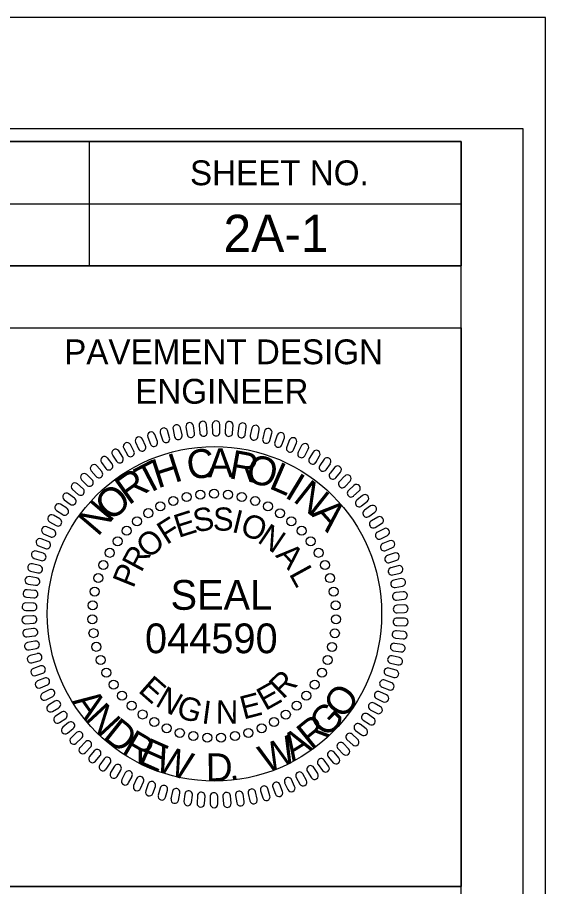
# Model space of a CAD drawing. Extents: x 1901670 to 1902225, y 193498 to 194278.
# Drawn here: x 1902123.59 to 1902134.24, y 194250.51 to 194268.01 of the extents above; entities that cross this region are included whole.
import ezdxf

# ---------------------------------------------------------------- set-up
doc = ezdxf.new("R2010")
doc.units = 0
for name, color, linetype in [('ENG SEALS CELL', 7, 'Continuous'), ('Scratch_Level_3', 7, 'Continuous'), ('Sheet Border Standard 30in CELL', 7, 'Continuous'), ('Sheet Cutting Line CELL', 7, 'Continuous'), ('Sheet Data Field CELL', 7, 'Continuous'), ('Sheet Plot Border Inside CELL', 7, 'Continuous'), ('Sheet Plot Border Outside CELL', 7, 'Continuous'), ('Sheet Sticker Exception Certification CELL', 7, 'Continuous')]:
    doc.layers.add(name, color=color, linetype=linetype)

msp = doc.modelspace()

# ---------------------------------------------------------------- linework, layer by layer
at = {"layer": 'ENG SEALS CELL'}
for p, q in [((1902126.913, 194259.604), (1902126.88, 194259.75)), ((1902126.993, 194259.766), (1902127.017, 194259.618)), ((1902127.166, 194259.642), (1902127.144, 194259.789)), ((1902127.258, 194259.798), (1902127.271, 194259.649)), ((1902127.422, 194259.661), (1902127.41, 194259.811)), ((1902127.524, 194259.811), (1902127.527, 194259.661)), ((1902127.678, 194259.663), (1902127.676, 194259.813)), ((1902127.791, 194259.805), (1902127.783, 194259.656)), ((1902127.934, 194259.647), (1902127.943, 194259.797)), ((1902128.056, 194259.782), (1902128.037, 194259.633)), ((1902128.188, 194259.614), (1902128.207, 194259.762)), ((1902126.417, 194259.476), (1902126.364, 194259.616)), ((1902126.474, 194259.647), (1902126.517, 194259.504)), ((1902126.663, 194259.548), (1902126.62, 194259.692)), ((1902126.732, 194259.716), (1902126.765, 194259.57)), ((1902128.319, 194259.739), (1902128.29, 194259.593)), ((1902128.44, 194259.563), (1902128.469, 194259.71)), ((1902128.579, 194259.678), (1902128.54, 194259.534)), ((1902128.686, 194259.494), (1902128.725, 194259.639)), ((1902128.834, 194259.6), (1902128.784, 194259.458)), ((1902125.944, 194259.28), (1902125.872, 194259.411)), ((1902125.976, 194259.458), (1902126.039, 194259.322)), ((1902126.177, 194259.386), (1902126.114, 194259.522)), ((1902126.222, 194259.562), (1902126.275, 194259.422)), ((1902128.928, 194259.409), (1902128.977, 194259.55)), ((1902129.082, 194259.504), (1902129.024, 194259.365)), ((1902129.163, 194259.306), (1902129.222, 194259.444)), ((1902125.718, 194259.158), (1902125.637, 194259.284)), ((1902125.718, 194259.158), (1902125.637, 194259.284)), ((1902125.738, 194259.338), (1902125.811, 194259.206)), ((1902129.323, 194259.39), (1902129.255, 194259.257)), ((1902129.39, 194259.187), (1902129.459, 194259.321)), ((1902129.556, 194259.261), (1902129.479, 194259.132)), ((1902125.291, 194259.049), (1902125.38, 194258.929)), ((1902125.291, 194259.049), (1902125.38, 194258.929)), ((1902125.502, 194259.02), (1902125.412, 194259.141)), ((1902125.502, 194259.02), (1902125.412, 194259.141)), ((1902125.509, 194259.201), (1902125.59, 194259.075)), ((1902125.509, 194259.201), (1902125.59, 194259.075)), ((1902129.609, 194259.053), (1902129.686, 194259.182)), ((1902129.779, 194259.115), (1902129.693, 194258.991)), ((1902125.083, 194258.882), (1902125.181, 194258.769)), ((1902125.083, 194258.882), (1902125.181, 194258.769)), ((1902125.296, 194258.868), (1902125.198, 194258.982)), ((1902125.296, 194258.868), (1902125.198, 194258.982)), ((1902129.817, 194258.904), (1902129.904, 194259.026)), ((1902129.991, 194258.953), (1902129.897, 194258.837)), ((1902124.887, 194258.7), (1902124.993, 194258.595)), ((1902125.101, 194258.701), (1902124.996, 194258.808)), ((1902130.015, 194258.741), (1902130.109, 194258.857)), ((1902130.192, 194258.778), (1902130.09, 194258.668)), ((1902124.918, 194258.522), (1902124.805, 194258.621)), ((1902130.201, 194258.564), (1902130.303, 194258.674)), ((1902130.38, 194258.589), (1902130.27, 194258.487)), ((1902124.748, 194258.331), (1902124.628, 194258.421)), ((1902124.705, 194258.506), (1902124.818, 194258.408)), ((1902130.373, 194258.376), (1902130.483, 194258.478)), ((1902130.554, 194258.387), (1902130.438, 194258.294)), ((1902124.592, 194258.127), (1902124.466, 194258.209)), ((1902124.537, 194258.3), (1902124.656, 194258.209)), ((1902130.533, 194258.175), (1902130.65, 194258.269)), ((1902130.714, 194258.174), (1902130.591, 194258.088)), ((1902124.383, 194258.082), (1902124.509, 194258)), ((1902130.678, 194257.963), (1902130.801, 194258.049)), ((1902124.245, 194257.854), (1902124.376, 194257.781)), ((1902124.45, 194257.913), (1902124.32, 194257.987)), ((1902130.858, 194257.95), (1902130.73, 194257.873)), ((1902124.324, 194257.691), (1902124.188, 194257.754)), ((1902130.808, 194257.743), (1902130.937, 194257.819)), ((1902130.987, 194257.716), (1902130.854, 194257.649)), ((1902124.214, 194257.46), (1902124.074, 194257.514)), ((1902124.124, 194257.616), (1902124.259, 194257.553)), ((1902130.922, 194257.513), (1902131.056, 194257.581)), ((1902131.099, 194257.475), (1902130.961, 194257.417)), ((1902124.019, 194257.372), (1902124.158, 194257.318)), ((1902131.02, 194257.277), (1902131.158, 194257.335)), ((1902123.932, 194257.12), (1902124.074, 194257.075)), ((1902124.119, 194257.221), (1902123.976, 194257.265)), ((1902131.193, 194257.226), (1902131.052, 194257.177)), ((1902124.043, 194256.977), (1902123.897, 194257.01)), ((1902131.101, 194257.033), (1902131.243, 194257.081)), ((1902131.271, 194256.97), (1902131.126, 194256.932)), ((1902123.861, 194256.862), (1902124.007, 194256.829)), ((1902131.165, 194256.785), (1902131.31, 194256.824)), ((1902123.81, 194256.601), (1902123.958, 194256.577)), ((1902123.982, 194256.728), (1902123.834, 194256.751)), ((1902131.331, 194256.711), (1902131.183, 194256.683)), ((1902123.939, 194256.475), (1902123.791, 194256.488)), ((1902131.212, 194256.533), (1902131.359, 194256.562)), ((1902131.371, 194256.447), (1902131.223, 194256.429)), ((1902123.777, 194256.337), (1902123.926, 194256.323)), ((1902131.24, 194256.279), (1902131.39, 194256.296)), ((1902123.762, 194256.071), (1902123.912, 194256.067)), ((1902123.915, 194256.22), (1902123.765, 194256.222)), ((1902131.394, 194256.181), (1902131.244, 194256.174)), ((1902123.908, 194255.963), (1902123.758, 194255.956)), ((1902131.398, 194255.915), (1902131.248, 194255.918)), ((1902131.251, 194256.022), (1902131.401, 194256.03)), ((1902123.766, 194255.804), (1902123.916, 194255.811)), ((1902131.244, 194255.766), (1902131.394, 194255.763)), ((1902123.919, 194255.708), (1902123.77, 194255.69)), ((1902123.788, 194255.538), (1902123.937, 194255.556)), ((1902131.383, 194255.649), (1902131.234, 194255.663)), ((1902123.948, 194255.453), (1902123.8, 194255.425)), ((1902131.35, 194255.384), (1902131.201, 194255.408)), ((1902131.22, 194255.511), (1902131.369, 194255.498)), ((1902123.829, 194255.275), (1902123.977, 194255.303)), ((1902123.994, 194255.2), (1902123.849, 194255.162)), ((1902131.177, 194255.258), (1902131.326, 194255.235)), ((1902123.888, 194255.015), (1902124.033, 194255.053)), ((1902131.298, 194255.123), (1902131.152, 194255.157)), ((1902124.059, 194254.952), (1902123.916, 194254.904)), ((1902131.228, 194254.866), (1902131.085, 194254.91)), ((1902131.117, 194255.009), (1902131.263, 194254.975)), ((1902123.965, 194254.76), (1902124.108, 194254.808)), ((1902124.139, 194254.71), (1902124.001, 194254.651)), ((1902131.04, 194254.764), (1902131.183, 194254.72)), ((1902124.06, 194254.511), (1902124.199, 194254.57)), ((1902130.946, 194254.527), (1902131.086, 194254.473)), ((1902131.141, 194254.614), (1902131.001, 194254.668)), ((1902124.237, 194254.473), (1902124.103, 194254.405)), ((1902124.172, 194254.269), (1902124.306, 194254.336)), ((1902131.036, 194254.369), (1902130.9, 194254.432)), ((1902124.352, 194254.244), (1902124.223, 194254.166)), ((1902130.914, 194254.132), (1902130.784, 194254.205)), ((1902130.836, 194254.296), (1902130.971, 194254.232)), ((1902124.301, 194254.036), (1902124.429, 194254.112)), ((1902124.482, 194254.022), (1902124.359, 194253.936)), ((1902130.776, 194253.904), (1902130.651, 194253.986)), ((1902130.709, 194254.072), (1902130.84, 194253.999)), ((1902124.445, 194253.812), (1902124.569, 194253.897)), ((1902124.626, 194253.811), (1902124.51, 194253.717)), ((1902130.567, 194253.859), (1902130.693, 194253.777)), ((1902124.605, 194253.599), (1902124.722, 194253.693)), ((1902130.411, 194253.656), (1902130.531, 194253.565)), ((1902130.623, 194253.686), (1902130.503, 194253.777)), ((1902124.786, 194253.61), (1902124.676, 194253.508)), ((1902124.78, 194253.397), (1902124.889, 194253.499)), ((1902130.242, 194253.463), (1902130.354, 194253.365)), ((1902130.454, 194253.479), (1902130.342, 194253.578)), ((1902124.959, 194253.421), (1902124.857, 194253.312)), ((1902124.968, 194253.208), (1902125.07, 194253.317)), ((1902130.058, 194253.284), (1902130.164, 194253.178)), ((1902130.272, 194253.285), (1902130.166, 194253.391)), ((1902125.145, 194253.245), (1902125.051, 194253.128)), ((1902125.168, 194253.032), (1902125.263, 194253.149)), ((1902129.863, 194253.118), (1902129.962, 194253.004)), ((1902130.077, 194253.104), (1902129.979, 194253.217)), ((1902125.343, 194253.082), (1902125.256, 194252.959)), ((1902125.381, 194252.872), (1902125.467, 194252.994)), ((1902125.551, 194252.932), (1902125.474, 194252.805)), ((1902129.658, 194252.965), (1902129.747, 194252.846)), ((1902129.869, 194252.937), (1902129.779, 194253.056)), ((1902125.604, 194252.726), (1902125.681, 194252.854)), ((1902125.77, 194252.798), (1902125.701, 194252.665)), ((1902129.422, 194252.648), (1902129.349, 194252.779)), ((1902129.441, 194252.828), (1902129.523, 194252.702)), ((1902129.651, 194252.784), (1902129.569, 194252.91)), ((1902125.837, 194252.596), (1902125.905, 194252.729)), ((1902125.997, 194252.68), (1902125.938, 194252.542)), ((1902126.078, 194252.482), (1902126.136, 194252.62)), ((1902126.232, 194252.578), (1902126.182, 194252.436)), ((1902128.982, 194252.6), (1902129.046, 194252.464)), ((1902129.183, 194252.527), (1902129.121, 194252.663)), ((1902129.216, 194252.706), (1902129.288, 194252.574)), ((1902126.326, 194252.386), (1902126.376, 194252.528)), ((1902126.473, 194252.492), (1902126.434, 194252.348)), ((1902126.581, 194252.308), (1902126.62, 194252.452)), ((1902126.72, 194252.423), (1902126.691, 194252.276)), ((1902126.84, 194252.246), (1902126.869, 194252.394)), ((1902128.428, 194252.27), (1902128.394, 194252.416)), ((1902128.496, 194252.437), (1902128.54, 194252.294)), ((1902128.686, 194252.338), (1902128.642, 194252.481)), ((1902128.743, 194252.51), (1902128.796, 194252.37)), ((1902128.938, 194252.424), (1902128.884, 194252.564)), ((1902126.971, 194252.372), (1902126.952, 194252.223)), ((1902127.103, 194252.204), (1902127.122, 194252.353)), ((1902127.225, 194252.338), (1902127.217, 194252.188)), ((1902127.369, 194252.18), (1902127.377, 194252.33)), ((1902127.481, 194252.322), (1902127.483, 194252.172)), ((1902127.636, 194252.175), (1902127.633, 194252.325)), ((1902127.738, 194252.324), (1902127.75, 194252.175)), ((1902127.902, 194252.188), (1902127.889, 194252.337)), ((1902127.993, 194252.345), (1902128.016, 194252.196)), ((1902128.166, 194252.22), (1902128.144, 194252.368)), ((1902128.246, 194252.382), (1902128.28, 194252.236))]:
    msp.add_line(p, q, dxfattribs=at)
for centre in [(1902126.736, 194258.277), (1902127.005, 194258.356), (1902127.281, 194258.404), (1902127.561, 194258.42), (1902127.842, 194258.404), (1902128.119, 194258.356), (1902128.388, 194258.277), (1902126.477, 194258.168), (1902128.646, 194258.167), (1902126.233, 194258.03), (1902128.89, 194258.029), (1902126.006, 194257.865), (1902129.117, 194257.864), (1902125.799, 194257.675), (1902129.324, 194257.675), (1902125.616, 194257.463), (1902129.508, 194257.463), (1902125.457, 194257.231), (1902129.666, 194257.231), (1902125.326, 194256.983), (1902129.797, 194256.983), (1902125.224, 194256.722), (1902129.899, 194256.721), (1902125.153, 194256.451), (1902129.97, 194256.45), (1902125.113, 194256.173), (1902130.01, 194256.172), (1902125.105, 194255.892), (1902130.018, 194255.892), (1902125.129, 194255.613), (1902129.994, 194255.612), (1902125.185, 194255.338), (1902129.938, 194255.337), (1902125.272, 194255.071), (1902129.851, 194255.071), (1902125.388, 194254.816), (1902129.735, 194254.815), (1902125.533, 194254.576), (1902129.59, 194254.575), (1902125.704, 194254.353), (1902129.418, 194254.353), (1902125.9, 194254.152), (1902129.223, 194254.152), (1902126.117, 194253.975), (1902129.006, 194253.974), (1902126.353, 194253.823), (1902128.769, 194253.823), (1902126.605, 194253.699), (1902126.869, 194253.605), (1902127.142, 194253.541), (1902127.98, 194253.541), (1902128.253, 194253.605), (1902128.518, 194253.699), (1902127.421, 194253.509), (1902127.701, 194253.509)]:
    msp.add_circle(centre, 0.091, dxfattribs=at)
for centre, start, end in [((1902126.547, 194259.67), 16.8349, 196.8343), ((1902126.806, 194259.733), 12.8349, 192.8343), ((1902127.068, 194259.778), 8.8349, 188.8343), ((1902127.334, 194259.804), 4.8349, 184.8343), ((1902127.6, 194259.812), 0.8349, 180.8343), ((1902127.867, 194259.801), 356.8349, 176.8343), ((1902128.132, 194259.772), 352.8349, 172.8343), ((1902128.394, 194259.724), 348.8349, 168.8343), ((1902126.293, 194259.589), 20.8349, 200.8343), ((1902126.839, 194259.587), 192.8343, 12.8349), ((1902127.091, 194259.63), 188.8343, 8.8349), ((1902127.346, 194259.655), 184.8343, 4.8349), ((1902127.602, 194259.662), 180.8343, 0.8349), ((1902127.858, 194259.652), 176.8343, 356.8349), ((1902128.113, 194259.623), 172.8343, 352.8349), ((1902128.365, 194259.577), 168.8343, 348.8349), ((1902128.652, 194259.659), 344.8349, 164.8343), ((1902128.905, 194259.575), 340.8349, 160.8343), ((1902125.805, 194259.375), 28.8349, 208.8343), ((1902126.045, 194259.49), 24.8349, 204.8343), ((1902126.346, 194259.449), 200.8343, 20.8349), ((1902126.59, 194259.526), 196.8343, 16.8349), ((1902128.613, 194259.514), 164.8343, 344.8349), ((1902128.856, 194259.433), 160.8343, 340.8349), ((1902129.152, 194259.474), 336.8349, 156.8343), ((1902129.391, 194259.355), 332.8349, 152.8343), ((1902125.573, 194259.243), 32.8349, 212.8343), ((1902125.573, 194259.243), 32.8349, 212.8343), ((1902125.877, 194259.243), 208.8343, 28.8349), ((1902126.108, 194259.354), 204.8343, 24.8349), ((1902129.093, 194259.336), 156.8343, 336.8349), ((1902129.322, 194259.222), 152.8343, 332.8349), ((1902129.621, 194259.221), 328.8349, 148.8343), ((1902125.351, 194259.095), 36.8349, 216.8343), ((1902125.351, 194259.095), 36.8349, 216.8343), ((1902125.654, 194259.117), 212.8343, 32.8349), ((1902125.654, 194259.117), 212.8343, 32.8349), ((1902129.543, 194259.093), 148.8343, 328.8349), ((1902129.841, 194259.071), 324.8349, 144.8343), ((1902125.14, 194258.932), 40.8349, 220.8343), ((1902125.14, 194258.932), 40.8349, 220.8343), ((1902125.441, 194258.975), 216.8343, 36.8349), ((1902125.441, 194258.975), 216.8343, 36.8349), ((1902129.755, 194258.948), 144.8343, 324.8349), ((1902130.05, 194258.905), 320.8349, 140.8343), ((1902124.941, 194258.754), 44.8349, 224.8343), ((1902125.047, 194258.648), 224.8343, 44.8349), ((1902125.238, 194258.818), 220.8343, 40.8349), ((1902125.238, 194258.818), 220.8343, 40.8349), ((1902129.956, 194258.789), 140.8343, 320.8349), ((1902130.248, 194258.726), 316.8349, 136.8343), ((1902124.755, 194258.564), 48.8349, 228.8343), ((1902124.868, 194258.465), 228.8343, 48.8349), ((1902130.145, 194258.617), 136.8343, 316.8349), ((1902130.432, 194258.533), 312.8349, 132.8343), ((1902124.583, 194258.36), 52.8349, 232.8343), ((1902130.322, 194258.431), 132.8343, 312.8349), ((1902130.602, 194258.328), 308.8349, 128.8343), ((1902124.425, 194258.145), 56.8349, 236.8343), ((1902124.702, 194258.27), 232.8343, 52.8349), ((1902130.485, 194258.234), 128.8343, 308.8349), ((1902130.757, 194258.112), 304.8349, 124.8343), ((1902124.282, 194257.92), 60.8349, 240.8343), ((1902124.55, 194258.063), 236.8343, 56.8349), ((1902130.634, 194258.026), 124.8343, 304.8349), ((1902124.413, 194257.847), 240.8343, 60.8349), ((1902130.769, 194257.808), 120.8343, 300.8349), ((1902130.898, 194257.885), 300.8349, 120.8343), ((1902124.156, 194257.685), 64.8349, 244.8343), ((1902124.292, 194257.622), 244.8343, 64.8349), ((1902130.888, 194257.581), 116.8343, 296.8349), ((1902131.021, 194257.649), 296.8349, 116.8343), ((1902124.046, 194257.442), 68.8349, 248.8343), ((1902131.129, 194257.405), 292.8349, 112.8343), ((1902124.186, 194257.388), 248.8343, 68.8349), ((1902130.99, 194257.346), 112.8343, 292.8349), ((1902123.954, 194257.192), 72.8349, 252.8343), ((1902124.097, 194257.148), 252.8343, 72.8349), ((1902131.077, 194257.105), 108.8343, 288.8349), ((1902131.218, 194257.154), 288.8349, 108.8343), ((1902123.879, 194256.937), 76.8349, 256.8343), ((1902124.025, 194256.902), 256.8343, 76.8349), ((1902131.291, 194256.897), 284.8349, 104.8343), ((1902131.146, 194256.859), 104.8343, 284.8349), ((1902123.822, 194256.676), 80.8349, 260.8343), ((1902123.97, 194256.652), 260.8343, 80.8349), ((1902131.197, 194256.608), 100.8343, 280.8349), ((1902131.345, 194256.636), 280.8349, 100.8343), ((1902123.784, 194256.412), 84.8349, 264.8343), ((1902123.933, 194256.399), 264.8343, 84.8349), ((1902131.231, 194256.354), 96.8343, 276.8349), ((1902131.38, 194256.372), 276.8349, 96.8343), ((1902123.764, 194256.147), 88.8349, 268.8343), ((1902123.913, 194256.143), 268.8343, 88.8349), ((1902131.248, 194256.098), 92.8343, 272.8349), ((1902131.397, 194256.106), 272.8349, 92.8343), ((1902123.762, 194255.88), 92.8349, 272.8343), ((1902123.912, 194255.887), 272.8343, 92.8349), ((1902131.246, 194255.842), 88.8343, 268.8349), ((1902131.396, 194255.839), 268.8349, 88.8343), ((1902123.779, 194255.614), 96.8349, 276.8343), ((1902123.928, 194255.632), 276.8343, 96.8349), ((1902131.227, 194255.587), 84.8343, 264.8349), ((1902131.376, 194255.573), 264.8349, 84.8343), ((1902123.815, 194255.35), 100.8349, 280.8343), ((1902123.962, 194255.378), 280.8343, 100.8349), ((1902131.189, 194255.333), 80.8343, 260.8349), ((1902131.337, 194255.309), 260.8349, 80.8343), ((1902124.014, 194255.127), 284.8343, 104.8349), ((1902123.869, 194255.089), 104.8349, 284.8343), ((1902131.135, 194255.083), 76.8343, 256.8349), ((1902131.281, 194255.049), 256.8349, 76.8343), ((1902123.941, 194254.832), 108.8349, 288.8343), ((1902124.083, 194254.88), 288.8343, 108.8349), ((1902131.063, 194254.837), 72.8343, 252.8349), ((1902131.206, 194254.793), 252.8349, 72.8343), ((1902124.169, 194254.639), 292.8343, 112.8349), ((1902130.973, 194254.597), 68.8343, 248.8349), ((1902124.031, 194254.581), 112.8349, 292.8343), ((1902131.113, 194254.543), 248.8349, 68.8343), ((1902124.138, 194254.337), 116.8349, 296.8343), ((1902124.272, 194254.405), 296.8343, 116.8349), ((1902130.868, 194254.364), 64.8343, 244.8349), ((1902131.004, 194254.3), 244.8349, 64.8343), ((1902124.262, 194254.101), 120.8349, 300.8343), ((1902124.391, 194254.178), 300.8343, 120.8349), ((1902130.746, 194254.139), 60.8343, 240.8349), ((1902124.525, 194253.96), 304.8343, 124.8349), ((1902130.609, 194253.922), 56.8343, 236.8349), ((1902130.877, 194254.066), 240.8349, 60.8343), ((1902124.402, 194253.874), 124.8349, 304.8343), ((1902124.674, 194253.752), 308.8343, 128.8349), ((1902130.735, 194253.84), 236.8349, 56.8343), ((1902124.558, 194253.658), 128.8349, 308.8343), ((1902124.838, 194253.554), 312.8343, 132.8349), ((1902130.457, 194253.716), 52.8343, 232.8349), ((1902130.577, 194253.625), 232.8349, 52.8343), ((1902124.728, 194253.452), 132.8349, 312.8343), ((1902125.015, 194253.369), 316.8343, 136.8349), ((1902130.292, 194253.521), 48.8343, 228.8349), ((1902130.404, 194253.422), 228.8349, 48.8343), ((1902124.912, 194253.26), 136.8349, 316.8343), ((1902125.204, 194253.196), 320.8343, 140.8349), ((1902130.112, 194253.338), 44.8343, 224.8349), ((1902130.218, 194253.231), 224.8349, 44.8343), ((1902125.109, 194253.08), 140.8349, 320.8343), ((1902125.405, 194253.038), 324.8343, 144.8349), ((1902129.921, 194253.167), 40.8343, 220.8349), ((1902130.019, 194253.054), 220.8349, 40.8343), ((1902125.318, 194252.915), 144.8349, 324.8343), ((1902125.616, 194252.893), 328.8343, 148.8349), ((1902129.505, 194252.869), 32.8343, 212.8349), ((1902129.718, 194253.011), 36.8343, 216.8349), ((1902129.808, 194252.891), 216.8349, 36.8343), ((1902125.539, 194252.765), 148.8349, 328.8343), ((1902125.837, 194252.764), 332.8343, 152.8349), ((1902129.282, 194252.742), 28.8343, 208.8349), ((1902129.586, 194252.743), 212.8349, 32.8343), ((1902125.769, 194252.63), 152.8349, 332.8343), ((1902126.067, 194252.65), 336.8343, 156.8349), ((1902126.304, 194252.552), 340.8343, 160.8349), ((1902128.814, 194252.537), 20.8343, 200.8349), ((1902129.052, 194252.631), 24.8343, 204.8349), ((1902129.355, 194252.611), 208.8349, 28.8343), ((1902126.008, 194252.512), 156.8349, 336.8343), ((1902126.254, 194252.411), 160.8349, 340.8343), ((1902126.547, 194252.472), 344.8343, 164.8349), ((1902126.795, 194252.408), 348.8343, 168.8349), ((1902127.047, 194252.362), 352.8343, 172.8349), ((1902127.301, 194252.334), 356.8343, 176.8349), ((1902127.557, 194252.323), 0.8343, 180.8349), ((1902127.813, 194252.331), 4.8343, 184.8349), ((1902128.068, 194252.356), 8.8343, 188.8349), ((1902128.321, 194252.399), 12.8343, 192.8349), ((1902128.569, 194252.459), 16.8343, 196.8349), ((1902128.867, 194252.397), 200.8349, 20.8343), ((1902129.115, 194252.495), 204.8349, 24.8343), ((1902126.507, 194252.327), 164.8349, 344.8343), ((1902126.766, 194252.261), 168.8349, 348.8343), ((1902127.028, 194252.214), 172.8349, 352.8343), ((1902128.091, 194252.208), 188.8349, 8.8343), ((1902128.354, 194252.253), 192.8349, 12.8343), ((1902128.613, 194252.316), 196.8349, 16.8343), ((1902127.293, 194252.184), 176.8349, 356.8343), ((1902127.559, 194252.174), 180.8349, 0.8343), ((1902127.826, 194252.181), 184.8349, 4.8343)]:
    msp.add_arc(centre, 0.0761, start, end, dxfattribs=at)
at = {"layer": 'Scratch_Level_3'}
msp.add_circle((1902127.567, 194256.002), 3.37, dxfattribs=at)
at = {"layer": 'Sheet Border Standard 30in CELL'}
for p, q in [((1902125.044, 194265.509), (1902125.044, 194263.009)), ((1902112.539, 194264.259), (1902132.544, 194264.259)), ((1902112.539, 194263.009), (1902132.544, 194263.009)), ((1902112.539, 194263.009), (1902132.544, 194263.009))]:
    msp.add_line(p, q, dxfattribs=at)
for points in [[(1902132.544, 194265.514), (1901982.544, 194265.514), (1901982.544, 194160.514), (1902132.544, 194160.514)], [(1902112.539, 194265.514), (1902132.544, 194265.514), (1902132.544, 194263.009), (1902112.539, 194263.009)], [(1902122.544, 194261.759), (1902132.544, 194261.759), (1902132.544, 194250.509), (1902122.544, 194250.509)]]:
    msp.add_lwpolyline(points, close=True, dxfattribs=at)
at = {"layer": 'Sheet Cutting Line CELL'}
msp.add_line((1902134.244, 194268.014), (1901965.844, 194268.014), dxfattribs=at)
at = {"layer": 'Sheet Plot Border Inside CELL'}
msp.add_lwpolyline([(1902133.794, 194265.769), (1901967.144, 194265.769), (1901967.144, 194160.259), (1902133.794, 194160.259)], close=True, dxfattribs=at)
at = {"layer": 'Sheet Plot Border Outside CELL'}
msp.add_lwpolyline([(1902134.244, 194268.014), (1901965.844, 194268.014), (1901965.844, 194158.014), (1902134.244, 194158.014)], close=True, dxfattribs=at)
at = {"layer": 'Sheet Sticker Exception Certification CELL'}
msp.add_line((1902112.539, 194250.509), (1902132.542, 194250.509), dxfattribs=at)

# ---------------------------------------------------------------- texts
at = {"layer": 'ENG SEALS CELL'}
for s, height, rotation, p in [('H', 0.582, 17.8424, (1902126.42, 194258.525)), ('C', 0.582, 7.9778, (1902127.049, 194258.698)), ('A', 0.582, 0.1945, (1902127.428, 194258.752)), ('R', 0.582, 349.6661, (1902127.839, 194258.737)), ('T', 0.582, 27.6116, (1902126.172, 194258.38)), ('O', 0.582, 345.727, (1902128.169, 194258.673)), ('L', 0.582, 336.5157, (1902128.643, 194258.54)), ('R', 0.582, 35.4408, (1902125.838, 194258.178)), ('I', 0.582, 328.9592, (1902128.961, 194258.363)), ('N', 0.582, 321.6624, (1902129.13, 194258.282)), ('O', 0.582, 42.8836, (1902125.489, 194257.842)), ('N', 0.582, 49.6124, (1902125.215, 194257.542)), ('A', 0.582, 312.1327, (1902129.499, 194258.004)), ('E', 0.467, 17.5898, (1902126.841, 194257.529)), ('S', 0.467, 10.2172, (1902127.178, 194257.639)), ('S', 0.467, 359.0087, (1902127.534, 194257.681)), ('I', 0.467, 346.1383, (1902127.898, 194257.655)), ('O', 0.467, 340.1508, (1902128.061, 194257.612)), ('F', 0.467, 32.3349, (1902126.604, 194257.384)), ('O', 0.467, 40.6085, (1902126.237, 194257.093)), ('N', 0.467, 326.0425, (1902128.413, 194257.455)), ('R', 0.467, 61.8256, (1902126.092, 194256.819)), ('A', 0.467, 312.7467, (1902128.785, 194257.17)), ('P', 0.467, 68.0589, (1902125.932, 194256.502)), ('L', 0.467, 298.716, (1902129.062, 194256.809)), ('SEAL', 0.5992, 360, (1902126.682, 194256.084)), ('E', 0.467, 318.6101, (1902126.011, 194254.441)), ('R', 0.467, 44.0241, (1902128.948, 194254.268)), ('N', 0.467, 329.8446, (1902126.354, 194254.163)), ('E', 0.467, 29.2789, (1902128.594, 194254.042)), ('O', 0.56, 54.3575, (1902130.178, 194253.86)), ('A', 0.56, 305.2118, (1902124.687, 194254.238)), ('G', 0.467, 342.6124, (1902126.773, 194253.934)), ('E', 0.467, 14.5337, (1902128.153, 194253.872)), ('N', 0.56, 312.6812, (1902124.941, 194253.879)), ('I', 0.467, 352.4162, (1902127.296, 194253.799)), ('N', 0.467, 359.7887, (1902127.596, 194253.792)), ('G', 0.56, 45.5995, (1902129.821, 194253.487)), ('D', 0.56, 321.4392, (1902125.295, 194253.504)), ('R', 0.56, 39.0595, (1902129.52, 194253.247)), ('R', 0.56, 329.6163, (1902125.673, 194253.206)), ('A', 0.56, 31.59, (1902129.145, 194253.016)), ('E', 0.56, 336.1564, (1902126.004, 194253.008)), ('W', 0.56, 21.5963, (1902128.603, 194252.788)), ('W', 0.56, 342.4429, (1902126.341, 194252.855)), ('D', 0.56, 0.8355, (1902127.397, 194252.629)), ('.', 0.56, 9.0126, (1902127.878, 194252.639))]:
    msp.add_text(s, height=height, rotation=rotation, dxfattribs=at).set_placement(p)
msp.add_text('044590', height=0.5994, dxfattribs=at).set_placement((1902126.167, 194255.209))
at = {"layer": 'Sheet Border Standard 30in CELL'}
for s, height, p in [('SHEET NO.', 0.5, (1902127.074, 194264.634)), ('PAVEMENT DESIGN', 0.50001, (1902124.538, 194261.029)), ('ENGINEER', 0.5, (1902125.969, 194260.234))]:
    msp.add_text(s, height=height, dxfattribs=at).set_placement(p)
at = {"layer": 'Sheet Data Field CELL'}
msp.add_text('2A-1', height=0.75, dxfattribs=at).set_placement((1902127.749, 194263.289))

doc.saveas('drawing.dxf')
